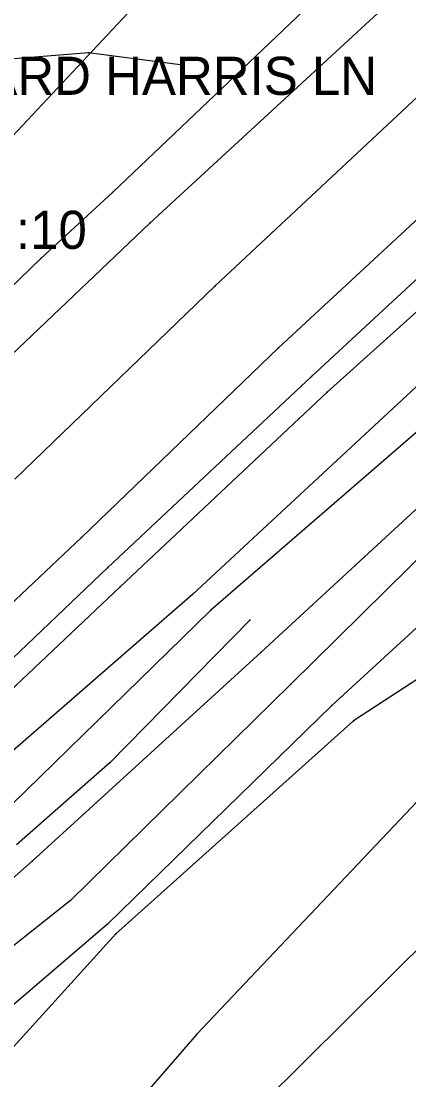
# Model space of a CAD drawing. Extents: x 1419505 to 1434054, y 1956910 to 1968644.
# Drawn here: x 1432631 to 1432681.8, y 1967114.9 to 1967253.6 of the extents above; entities that cross this region are included whole.
import ezdxf

# ---------------------------------------------------------------- set-up
doc = ezdxf.new("R2010")
doc.units = 0
for name, color, linetype in [('S_BREAKLINE', 7, 'Continuous'), ('S_DITCHLINE', 7, 'Continuous'), ('S_EDGE_PAVEMENT', 7, 'Continuous'), ('S_GRD_PT_SYM', 7, 'Continuous'), ('S_PAVEMENT_CROWN', 7, 'Continuous'), ('S_RDW_PT_SYM', 7, 'Continuous'), ('S_SHOULDER', 7, 'Continuous'), ('S_SIDE_DRAIN', 7, 'Continuous'), ('S_SIDE_DRAIN_ANNOT', 7, 'Continuous'), ('S_SURVEY_TEXT_ANNOT', 7, 'Continuous')]:
    doc.layers.add(name, color=color, linetype=linetype)

msp = doc.modelspace()

# ---------------------------------------------------------------- linework, layer by layer
at = {"layer": 'S_BREAKLINE'}
for p, q in [((1432702.8185, 1967233.551), (1432671.1125, 1967205.0171)), ((1432683.3903, 1967206.2832), (1432653.4303, 1967178.4864)), ((1432671.1125, 1967205.0171), (1432643.9597, 1967179.4935)), ((1432695.7681, 1967195.7405), (1432666.2962, 1967166.6937)), ((1432700.5314, 1967190.4132), (1432671.7145, 1967163.9195)), ((1432708.7459, 1967184.2758), (1432674.5747, 1967161.9113)), ((1432643.9597, 1967179.4935), (1432596.1826, 1967134.4326)), ((1432653.4303, 1967178.4864), (1432623.9264, 1967152.8098)), ((1432660.9628, 1967175.1332), (1432642.6626, 1967156.438)), ((1432666.2962, 1967166.6937), (1432637.4423, 1967138.3568)), ((1432671.7145, 1967163.9195), (1432642.2756, 1967135.2736)), ((1432674.5747, 1967161.9113), (1432643.4087, 1967133.9795)), ((1432642.6626, 1967156.438), (1432630.3788, 1967145.6873)), ((1432684.5443, 1967153.0358), (1432654.0264, 1967120.8287)), ((1432693.7989, 1967142.7271), (1432662.3989, 1967111.5991)), ((1432637.4423, 1967138.3568), (1432600.7269, 1967109.3)), ((1432642.2756, 1967135.2736), (1432606.4443, 1967104.5466)), ((1432643.4087, 1967133.9795), (1432611.2926, 1967098.7163)), ((1432654.0264, 1967120.8287), (1432623.2214, 1967085.4774))]:
    msp.add_line(p, q, dxfattribs=at)
at = {"layer": 'S_DITCHLINE'}
for p, q in [((1432686.8685, 1967203.28), (1432655.8315, 1967176.4353)), ((1432692.7679, 1967198.8857), (1432662.4429, 1967170.9099)), ((1432655.8315, 1967176.4353), (1432627.7517, 1967149.0445)), ((1432662.4429, 1967170.9099), (1432632.419, 1967143.5232)), ((1432632.419, 1967143.5232), (1432598.2208, 1967113.5432))]:
    msp.add_line(p, q, dxfattribs=at)
at = {"layer": 'S_EDGE_PAVEMENT'}
for p, q in [((1432680.2871, 1967257.0325), (1432647.846, 1967227.1466)), ((1432696.4981, 1967240.2604), (1432664.7191, 1967210.7975)), ((1432647.846, 1967227.1466), (1432623.4514, 1967203.9651)), ((1432664.7191, 1967210.7975), (1432638.8644, 1967185.9299)), ((1432638.8644, 1967185.9299), (1432591.8854, 1967141.659))]:
    msp.add_line(p, q, dxfattribs=at)
at = {"layer": 'S_GRD_PT_SYM'}
for points in [[(1432671.1125, 1967205.0171), (1432671.1125, 1967205.0671), (1432671.1125, 1967205.0171), (1432671.0625, 1967205.0171), (1432671.1125, 1967205.0171), (1432671.1125, 1967204.9671), (1432671.1125, 1967205.0171), (1432671.1625, 1967205.0171)], [(1432643.9597, 1967179.4935), (1432643.9597, 1967179.5435), (1432643.9597, 1967179.4935), (1432643.9097, 1967179.4935), (1432643.9597, 1967179.4935), (1432643.9597, 1967179.4435), (1432643.9597, 1967179.4935), (1432644.0097, 1967179.4935)], [(1432653.4303, 1967178.4864), (1432653.4303, 1967178.5364), (1432653.4303, 1967178.4864), (1432653.3803, 1967178.4864), (1432653.4303, 1967178.4864), (1432653.4303, 1967178.4364), (1432653.4303, 1967178.4864), (1432653.4803, 1967178.4864)], [(1432655.8315, 1967176.4353), (1432655.8315, 1967176.4853), (1432655.8315, 1967176.4353), (1432655.7815, 1967176.4353), (1432655.8315, 1967176.4353), (1432655.8315, 1967176.3853), (1432655.8315, 1967176.4353), (1432655.8815, 1967176.4353)], [(1432660.9628, 1967175.1332), (1432660.9628, 1967175.1832), (1432660.9628, 1967175.1332), (1432660.9128, 1967175.1332), (1432660.9628, 1967175.1332), (1432660.9628, 1967175.0832), (1432660.9628, 1967175.1332), (1432661.0128, 1967175.1332)], [(1432662.4429, 1967170.9099), (1432662.4429, 1967170.9599), (1432662.4429, 1967170.9099), (1432662.3929, 1967170.9099), (1432662.4429, 1967170.9099), (1432662.4429, 1967170.8599), (1432662.4429, 1967170.9099), (1432662.4929, 1967170.9099)], [(1432666.2962, 1967166.6937), (1432666.2962, 1967166.7437), (1432666.2962, 1967166.6937), (1432666.2462, 1967166.6937), (1432666.2962, 1967166.6937), (1432666.2962, 1967166.6437), (1432666.2962, 1967166.6937), (1432666.3462, 1967166.6937)], [(1432671.7145, 1967163.9195), (1432671.7145, 1967163.9695), (1432671.7145, 1967163.9195), (1432671.6645, 1967163.9195), (1432671.7145, 1967163.9195), (1432671.7145, 1967163.8695), (1432671.7145, 1967163.9195), (1432671.7645, 1967163.9195)], [(1432674.5747, 1967161.9113), (1432674.5747, 1967161.9613), (1432674.5747, 1967161.9113), (1432674.5247, 1967161.9113), (1432674.5747, 1967161.9113), (1432674.5747, 1967161.8613), (1432674.5747, 1967161.9113), (1432674.6247, 1967161.9113)], [(1432642.6626, 1967156.438), (1432642.6626, 1967156.488), (1432642.6626, 1967156.438), (1432642.6126, 1967156.438), (1432642.6626, 1967156.438), (1432642.6626, 1967156.388), (1432642.6626, 1967156.438), (1432642.7126, 1967156.438)], [(1432632.419, 1967143.5232), (1432632.419, 1967143.5732), (1432632.419, 1967143.5232), (1432632.369, 1967143.5232), (1432632.419, 1967143.5232), (1432632.419, 1967143.4732), (1432632.419, 1967143.5232), (1432632.469, 1967143.5232)], [(1432637.4423, 1967138.3568), (1432637.4423, 1967138.4068), (1432637.4423, 1967138.3568), (1432637.3923, 1967138.3568), (1432637.4423, 1967138.3568), (1432637.4423, 1967138.3068), (1432637.4423, 1967138.3568), (1432637.4923, 1967138.3568)], [(1432642.2756, 1967135.2736), (1432642.2756, 1967135.3236), (1432642.2756, 1967135.2736), (1432642.2256, 1967135.2736), (1432642.2756, 1967135.2736), (1432642.2756, 1967135.2236), (1432642.2756, 1967135.2736), (1432642.3256, 1967135.2736)], [(1432643.4087, 1967133.9795), (1432643.4087, 1967134.0295), (1432643.4087, 1967133.9795), (1432643.3587, 1967133.9795), (1432643.4087, 1967133.9795), (1432643.4087, 1967133.9295), (1432643.4087, 1967133.9795), (1432643.4587, 1967133.9795)], [(1432654.0264, 1967120.8287), (1432654.0264, 1967120.8787), (1432654.0264, 1967120.8287), (1432653.9764, 1967120.8287), (1432654.0264, 1967120.8287), (1432654.0264, 1967120.7787), (1432654.0264, 1967120.8287), (1432654.0764, 1967120.8287)]]:
    msp.add_lwpolyline(points, dxfattribs=at)
at = {"layer": 'S_PAVEMENT_CROWN'}
for p, q in [((1432639.8124, 1967249.491), (1432612.2587, 1967247.2059)), ((1432652.1792, 1967247.8369), (1432639.8124, 1967249.491)), ((1432688.4756, 1967248.882), (1432656.4325, 1967218.923)), ((1432656.4325, 1967218.923), (1432630.1618, 1967193.5964))]:
    msp.add_line(p, q, dxfattribs=at)
at = {"layer": 'S_RDW_PT_SYM'}
for points in [[(1432639.8124, 1967249.491), (1432639.8124, 1967249.541), (1432639.8124, 1967249.491), (1432639.7624, 1967249.491), (1432639.8124, 1967249.491), (1432639.8124, 1967249.441), (1432639.8124, 1967249.491), (1432639.8624, 1967249.491)], [(1432652.1792, 1967247.8369), (1432652.1792, 1967247.8869), (1432652.1792, 1967247.8369), (1432652.1292, 1967247.8369), (1432652.1792, 1967247.8369), (1432652.1792, 1967247.7869), (1432652.1792, 1967247.8369), (1432652.2292, 1967247.8369)], [(1432642.9376, 1967231.1818), (1432642.9376, 1967231.2318), (1432642.9376, 1967231.1818), (1432642.8876, 1967231.1818), (1432642.9376, 1967231.1818), (1432642.9376, 1967231.1318), (1432642.9376, 1967231.1818), (1432642.9876, 1967231.1818)], [(1432647.846, 1967227.1466), (1432647.846, 1967227.1966), (1432647.846, 1967227.1466), (1432647.796, 1967227.1466), (1432647.846, 1967227.1466), (1432647.846, 1967227.0966), (1432647.846, 1967227.1466), (1432647.896, 1967227.1466)], [(1432633.559, 1967222.5133), (1432633.559, 1967222.5633), (1432633.559, 1967222.5133), (1432633.509, 1967222.5133), (1432633.559, 1967222.5133), (1432633.559, 1967222.4633), (1432633.559, 1967222.5133), (1432633.609, 1967222.5133)], [(1432656.4325, 1967218.923), (1432656.4325, 1967218.973), (1432656.4325, 1967218.923), (1432656.3825, 1967218.923), (1432656.4325, 1967218.923), (1432656.4325, 1967218.873), (1432656.4325, 1967218.923), (1432656.4825, 1967218.923)], [(1432664.7191, 1967210.7975), (1432664.7191, 1967210.8475), (1432664.7191, 1967210.7975), (1432664.6691, 1967210.7975), (1432664.7191, 1967210.7975), (1432664.7191, 1967210.7475), (1432664.7191, 1967210.7975), (1432664.7691, 1967210.7975)], [(1432669.0553, 1967207.0513), (1432669.0553, 1967207.1013), (1432669.0553, 1967207.0513), (1432669.0053, 1967207.0513), (1432669.0553, 1967207.0513), (1432669.0553, 1967207.0013), (1432669.0553, 1967207.0513), (1432669.1053, 1967207.0513)], [(1432638.8644, 1967185.9299), (1432638.8644, 1967185.9799), (1432638.8644, 1967185.9299), (1432638.8144, 1967185.9299), (1432638.8644, 1967185.9299), (1432638.8644, 1967185.8799), (1432638.8644, 1967185.9299), (1432638.9144, 1967185.9299)], [(1432642.3396, 1967181.9996), (1432642.3396, 1967182.0496), (1432642.3396, 1967181.9996), (1432642.2896, 1967181.9996), (1432642.3396, 1967181.9996), (1432642.3396, 1967181.9496), (1432642.3396, 1967181.9996), (1432642.3896, 1967181.9996)]]:
    msp.add_lwpolyline(points, dxfattribs=at)
at = {"layer": 'S_SHOULDER'}
for p, q in [((1432675.1507, 1967261.7868), (1432642.9376, 1967231.1818)), ((1432700.4054, 1967236.1191), (1432669.0553, 1967207.0513)), ((1432642.9376, 1967231.1818), (1432633.559, 1967222.5133)), ((1432633.559, 1967222.5133), (1432618.7421, 1967208.2263)), ((1432669.0553, 1967207.0513), (1432642.3396, 1967181.9996)), ((1432642.3396, 1967181.9996), (1432595.0026, 1967137.1207))]:
    msp.add_line(p, q, dxfattribs=at)
at = {"layer": 'S_SIDE_DRAIN'}
msp.add_line((1432655.2104, 1967265.593), (1432620.6352, 1967228.7737), dxfattribs=at)

# ---------------------------------------------------------------- texts
at = {"layer": 'S_SIDE_DRAIN_ANNOT'}
msp.add_text('CN:10', height=5, dxfattribs=at).set_placement((1432620.6352, 1967223.7737))
at = {"layer": 'S_SURVEY_TEXT_ANNOT'}
msp.add_text('WARD HARRIS LN', height=5, dxfattribs=at).set_placement((1432619.7001, 1967243.964))

doc.saveas('drawing.dxf')
